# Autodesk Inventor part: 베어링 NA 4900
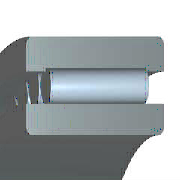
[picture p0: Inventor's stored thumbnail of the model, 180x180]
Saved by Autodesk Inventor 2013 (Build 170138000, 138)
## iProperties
Created: 2014-07
Part Number: 베어링 NA 4900
Material: Steel, Mild
Description: 니들 롤러 베어링 - 경계 치수 및 공차
Document SubType Name: Modeling
Standard: KS B 2029
Designer: KYOUNG IL JANG
Standards Organization: KS
Language: ko-KR
Size Designation: NA 4900 - 10 x 22 x 13
Categories: <MemberInstance><Categories><Category DisplayName="샤프트 부품" InternalName="7f7aeb1f-a693-4053-b835-cee3144e0d98" Mnemonic="SHFT"><Category DisplayName="베어링" Inter
Density: 7.86 g/cm^3
Mass: 23.8214 g
Surface Area: 38.613 cm^2
Volume: 3.03071 cm^3
Company: 한국ATC센터
IsCustomPart: 0
Author: KYOUNG IL JANG
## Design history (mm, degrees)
revolve "본체" stored, may be unused: angle "d17" = 90 deg
revolve "롤러" stored, may be unused: angle "d18" = 90 deg
pattern_circular "IDS_ARRAYROLLER[SIMPL:T]" dims angle "d2" = 360 deg
body "Solid1"
sketch "스케치"
  geometry: L1 (1.857, 9)-(11.143, 9); L2 (11.143, 9)-(11.143, 7); L3 (13, 7)-(0, 7); L4 (1.857, 7)-(1.857, 9); L5 (1.857, 8)-(11.143, 8); L6 (6.5, 8)-(6.5, 7); L7 (0, 5)-(13, 5); L8 (0, 11)-(13, 11); L9 (13, 5)-(13, 7); L10 (13, 8.8)-(13, 11); L11 (1.857, 8.8)-(0, 8.8); L12 (11.143, 8.8)-(13, 8.8); L13 (-6, 0)-(36, 0) reference; L14 (0, -1.9)-(0, 14.9) reference
  constraints: 24 end point, 8 point on line, 3 midpoint, 3 parallel, 3 perpendicular, 2 symmetric about line, 1 horizontal, 1 other
  dimensions: "d6" = 10 diameter of L7 L13 (= WD); "d7" = 14 diameter of L3 L13 (= KID1); "d8" = 22 diameter of L8 L13 (= BD); "d9" = 16 diameter of L6.start L13 (= 0.5 x WD + 0.5 x BD); "d10" = 17.6 diameter of L12 L13 (= 0.9 x BD + 0.9 x WD - 0.8 x KID1); "d11" = 18 diameter of L1 L13 (= BD + WD - KID1); "d12" = 1.85714 distance between parallel lines of L14 L4 (= 0.142857 x KB); "d13" = 13 distance between parallel lines of L14 L9 (= KB); "d14" = 11.14286 distance between parallel lines of L14 L2 (= 0.857143 x KB)
fillet "모깎기1" dims "d0" = 0.3 (= KRS)
other parameters: "WD" = 10 [user parameter; used in 6 equation terms], "BD" = 22 [user parameter; used in 6 equation terms], "KB" = 13 [user parameter; used in 3 equation terms], "KID1" = 14 [user parameter; used in 4 equation terms], "KRS" = 0.3 [user parameter; used in 1 equation term], "d3" = 0, "d4" = 0, "d5" = 0, "d15" = 0, "d16" = 0, "BC0" = 9150000 [user parameter], "WR" = 5 (= 0.5 x WD) [user parameter], "BBA" = 0 [user parameter], "BC" = 8150000 [user parameter], "BR" = 11 (= 0.5 x BD) [user parameter]
